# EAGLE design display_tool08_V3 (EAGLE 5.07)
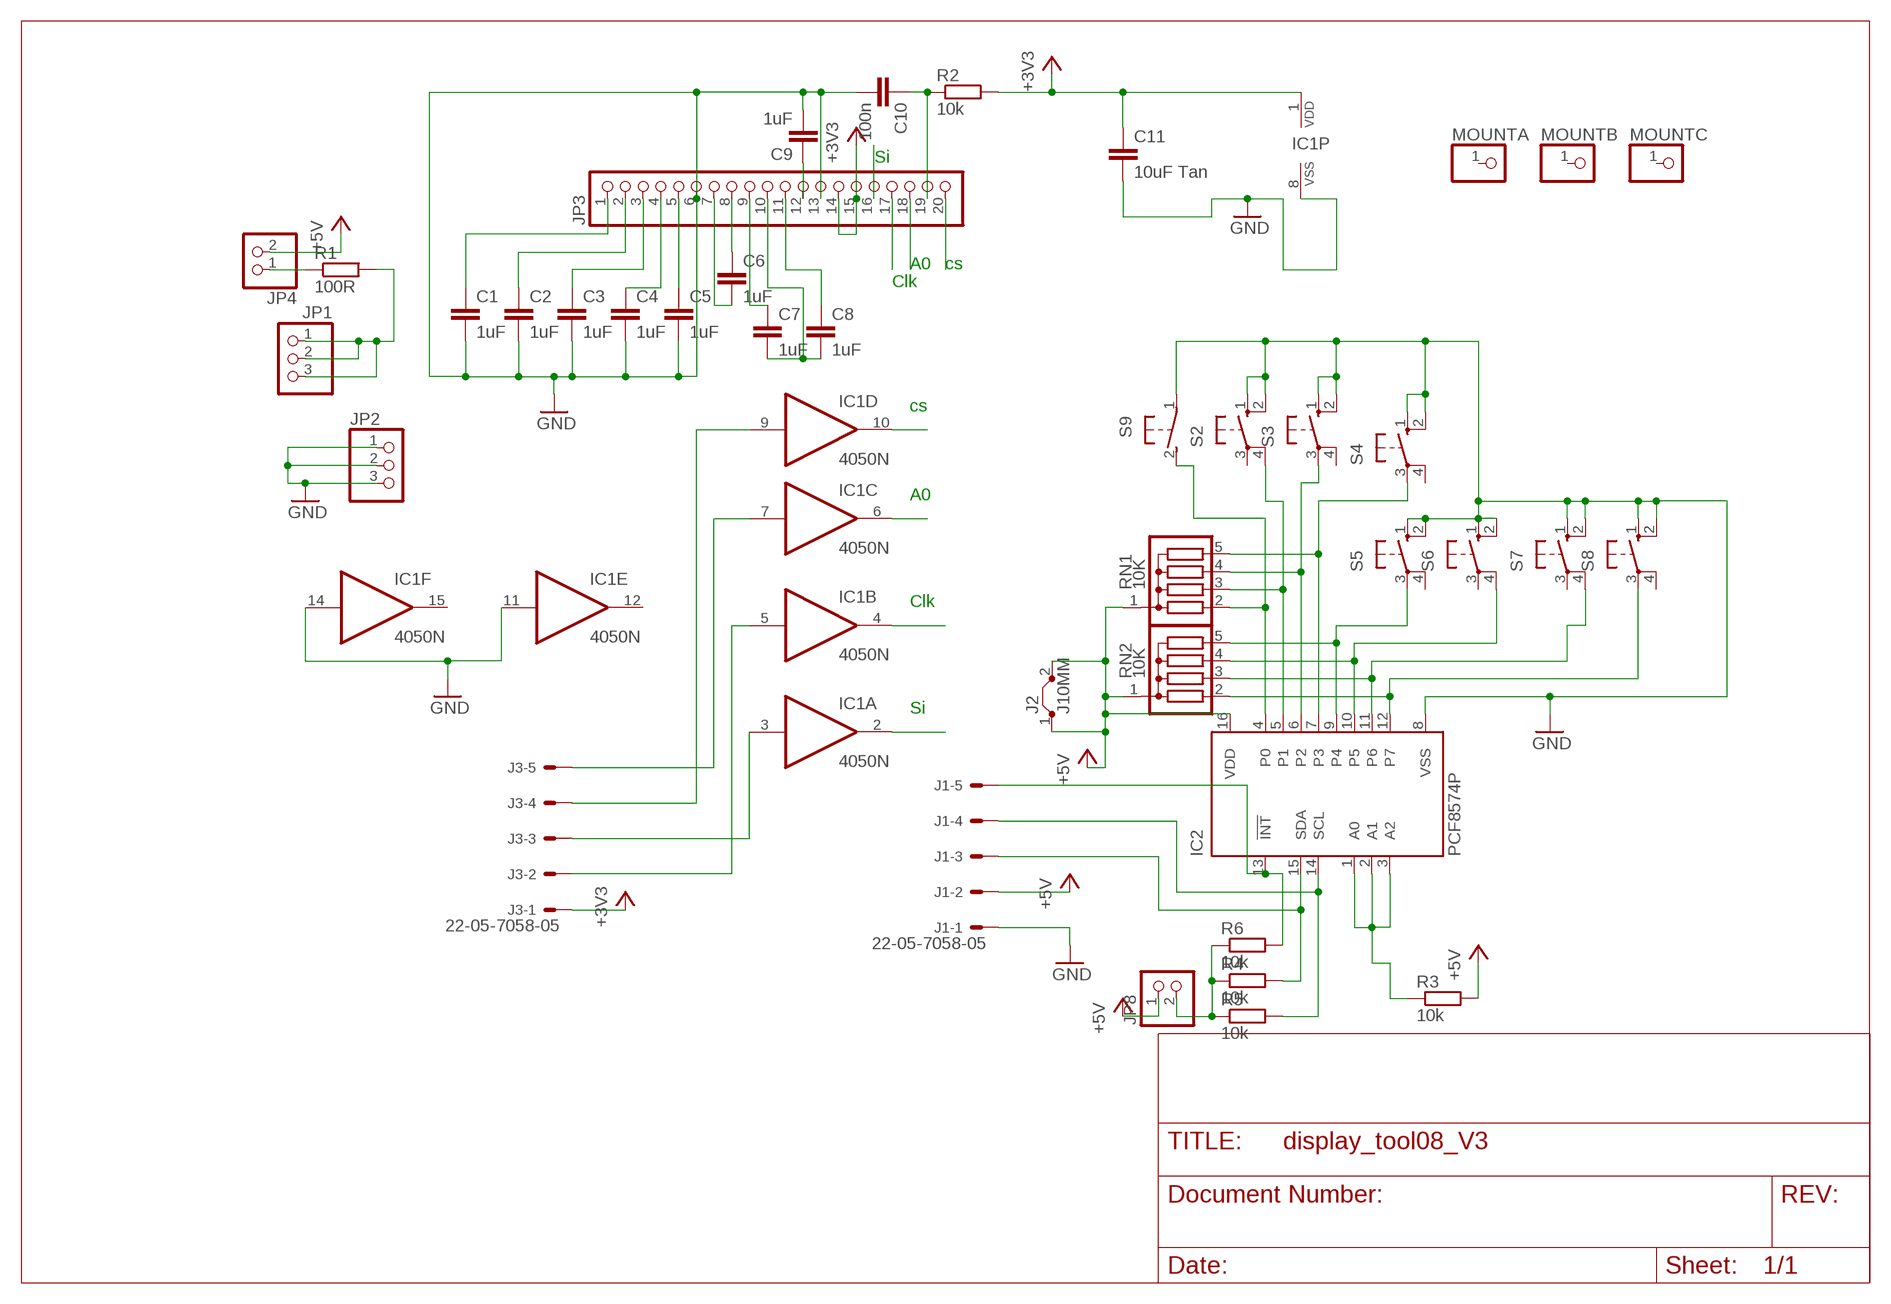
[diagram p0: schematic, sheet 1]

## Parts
C1  1uF  C-EU025-025X050  [C025-025X050]
C2  1uF  C-EU025-025X050  [C025-025X050]
C3  1uF  C-EU025-025X050  [C025-025X050]
C4  1uF  C-EU025-025X050  [C025-025X050]
C5  1uF  C-EU025-025X050  [C025-025X050]
C6  1uF  C-EU025-025X050  [C025-025X050]
C7  1uF  C-EU025-025X050  [C025-025X050]
C8  1uF  C-EU025-025X050  [C025-025X050]
C9  1uF  C-EU025-025X050  [C025-025X050]
C10  100n  C-EU025-025X050  [C025-025X050]
C11  10uF Tan  C-EU025-025X050  [C025-025X050]
IC1  4050N  [DIL16]
IC2  PCF8574P  [DIL16]
J1  22-05-7058-05  [7395-05]
J2  J10MM  [10]
J3  22-05-7058-05  [7395-05]
JP1  PINHD-1X3  [1X03]
JP2  PINHD-1X3  [1X03]
JP3  PINHD-1X20  [1X20]
JP4  PINHD-1X2  [1X02]
JP8  PINHD-1X2  [1X02]
MOUNTA  PINHD-1X1  [1X01]
MOUNTB  PINHD-1X1  [1X01]
MOUNTC  PINHD-1X1  [1X01]
R1  100R  R-EU_0309/12  [0309/12]
R2  10k  R-EU_0309/12  [0309/12]
R3  10k  R-EU_0207/7  [0207/7]
R4  10k  R-EU_0207/7  [0207/7]
R5  10k  R-EU_0207/7  [0207/7]
R6  10k  R-EU_0207/7  [0207/7]
RN1  10K  G04R  [SIL5]
RN2  10K  G04R  [SIL5]
S2  10-XX  [B3F-10XX]
S3  10-XX  [B3F-10XX]
S4  10-XX  [B3F-10XX]
S5  10-XX  [B3F-10XX]
S6  10-XX  [B3F-10XX]
S7  10-XX  [B3F-10XX]
S8  10-XX  [B3F-10XX]
S9  31-XX  [B3F-31XX]

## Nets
+3V3: C11.1 IC1.1(P:VDD) J3.1 JP3.14 JP3.15 R2.2
+5V: IC2.16(VDD) J1.2 J2.1 J2.2 JP4.2 JP8.1 R3.2 RN1.1 RN2.1
A0: IC1.6(C:O) JP3.18
CLK: IC1.4(B:O) JP3.17
CS [signal]: IC1.10(D:O) JP3.20
GND: C1.2 C2.2 C3.2 C4.2 C5.2 C9.2 C10.2 C11.2 IC1.8(P:VSS) IC1.11(E:I) IC1.14(F:I) IC2.8(VSS) J1.1 JP2.1 JP2.2 JP2.3 JP3.6 JP3.13 S2.1(S) S2.2(S1) S3.1(S) S3.2(S1) S4.1(S) S4.2(S1) S5.1(S) S5.2(S1) S6.1(S) S6.2(S1) S7.1(S) S7.2(S1) S8.1(S) S8.2(S1) S9.1(P)
N$1: JP4.1 R1.1
N$2: JP1.1 JP1.2 JP1.3 R1.2
N$3: IC2.7(P3) RN1.5 S4.3(P)
N$4: IC2.12(P7) RN2.2 S8.3(P)
N$5: C1.1 JP3.1
N$6: C2.1 JP3.2
N$7: C3.1 JP3.3
N$8: C4.1 JP3.4
N$9: C5.1 JP3.5
N$10: IC2.6(P2) RN1.4 S3.3(P)
N$11: IC2.11(P6) RN2.3 S7.4(P1)
N$12: C6.2 JP3.7
N$13: C6.1 JP3.8
N$14: C7.2 C8.2 JP3.10
N$15: IC2.5(P1) RN1.3 S2.4(P1)
N$16: C7.1 JP3.9
N$17: C8.1 JP3.11
N$18: C9.1 JP3.12
N$19: C10.1 JP3.19 R2.1
N$20: IC2.10(P5) RN2.4 S6.4(P1)
N$21: IC2.4(P0) RN1.2 S9.2(S)
N$22: IC2.9(P4) RN2.5 S5.3(P)
N$25 [signal]: IC1.3(A:I) J3.3
N$26 [signal]: IC1.5(B:I) J3.2
N$27 [signal]: IC1.7(C:I) J3.5
N$28 [signal]: IC1.9(D:I) J3.4
N$30: IC2.13(!INT) J1.5 R6.2
N$31: IC2.1(A0) IC2.2(A1) IC2.3(A2) R3.1
N$35: JP8.2 R4.1 R5.1 R6.1
SCL: IC2.14(SCL) J1.4 R5.2
SDA: IC2.15(SDA) J1.3 R4.2
SI: IC1.2(A:O) JP3.16
Unconnected: IC1.12(E:O) IC1.15(F:O) MOUNTA.1 MOUNTB.1 MOUNTC.1 S2.3(P) S3.4(P1) S4.4(P1) S5.4(P1) S6.3(P) S7.3(P) S8.4(P1)

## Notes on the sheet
- Si
- A0 | cs
- Clk
- cs
- A0
- Clk
- Si

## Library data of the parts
C1-C11 = rcl:C-EU: CAPACITOR, European symbol
IC1 = 40xx:4050: Hex non-inverting BUFFER
IC2 = micro-philips:PCF8574: I2C-Bus Remote 8-bit I/O expander http://www.semiconductors.philips.com/acrobat_download/datasheets/PCF8574_4.pdf
J1 J3 = con-molex:22-?-05: CONNECTOR wire to board 2.54 mm (.1 inch) pitch header
J2 = jumper:J: Bridge
JP1 JP2 = pinhead:PINHD-1X3: PIN HEADER
JP3 = pinhead:PINHD-1X20: PIN HEADER
JP4 JP8 = pinhead:PINHD-1X2: PIN HEADER
MOUNTA MOUNTB MOUNTC = pinhead:PINHD-1X1: PIN HEADER
R1-R6 = rcl:R-EU_: RESISTOR, European symbol
RN1 RN2 = resistor-sil:G04R: SIL RESISTOR
S2-S8 = switch-omron:10-XX: OMRON SWITCH
S9 = switch-omron:31-XX: OMRON SWITCH

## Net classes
0 default: width 1.016 mm, drill 1.016 mm, clearance 0.635 mm
1 signal: width 0.889 mm, drill 1.016 mm, clearance 0.635 mm to class 0, clearance 0.635 mm

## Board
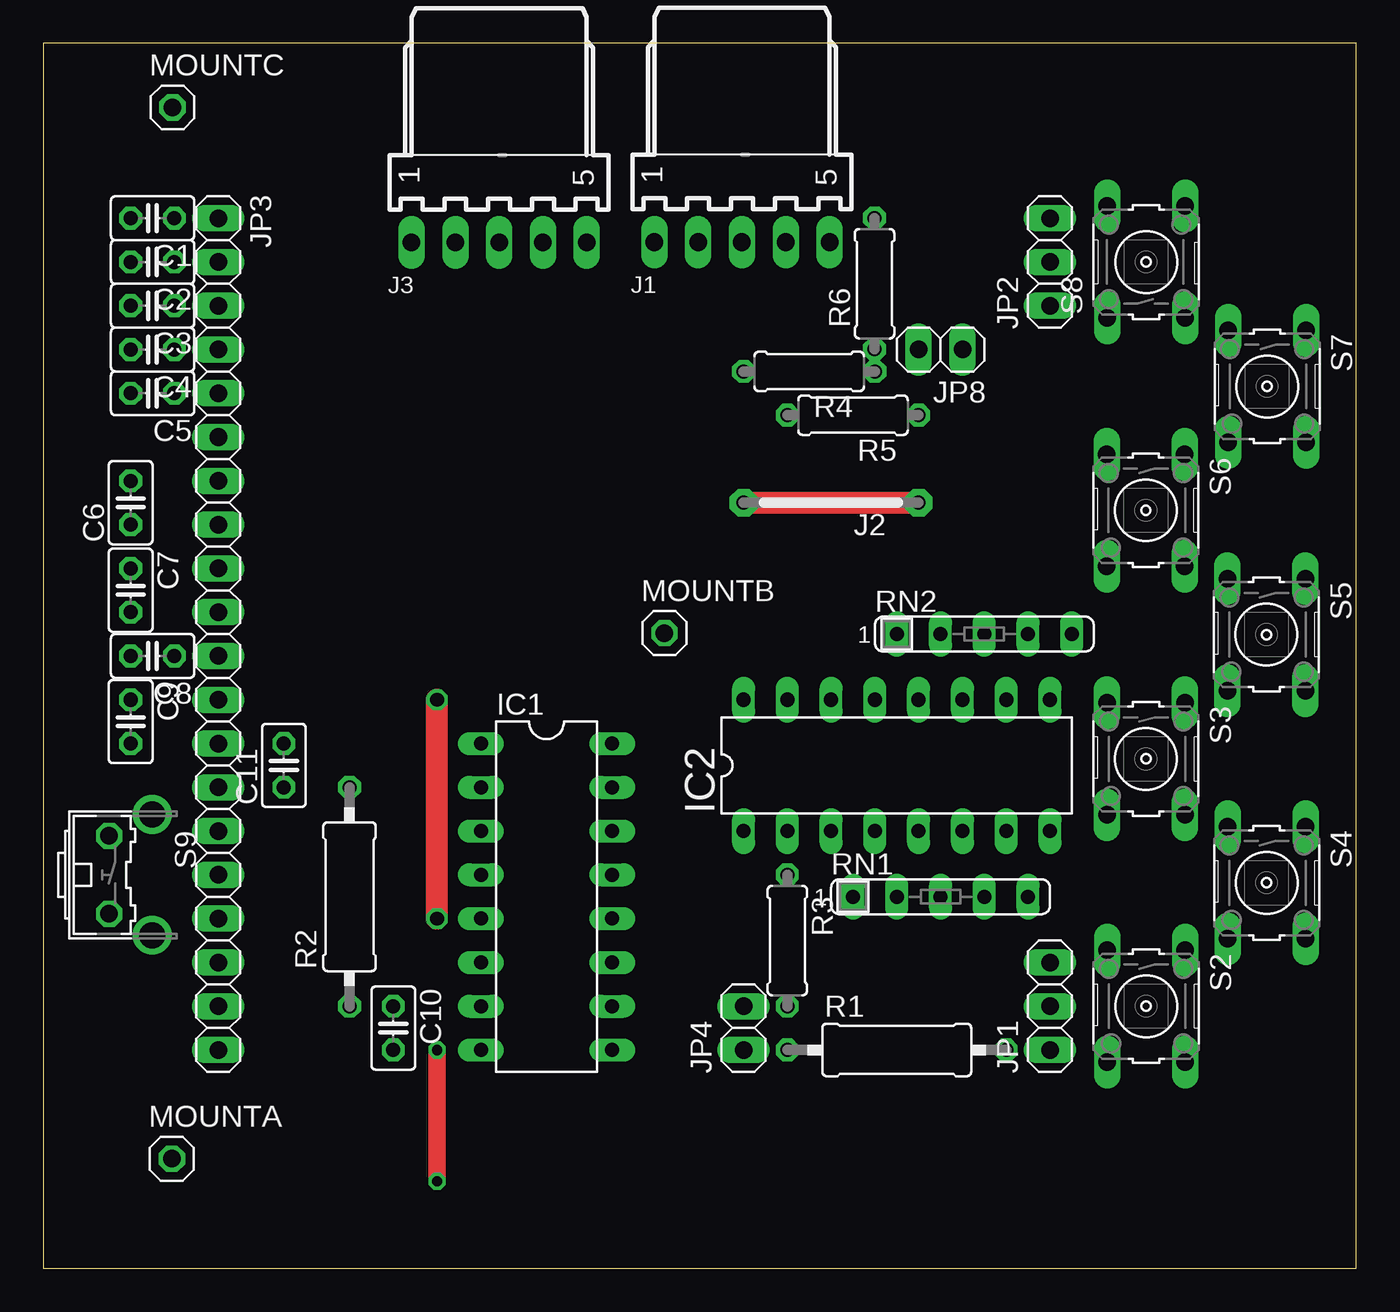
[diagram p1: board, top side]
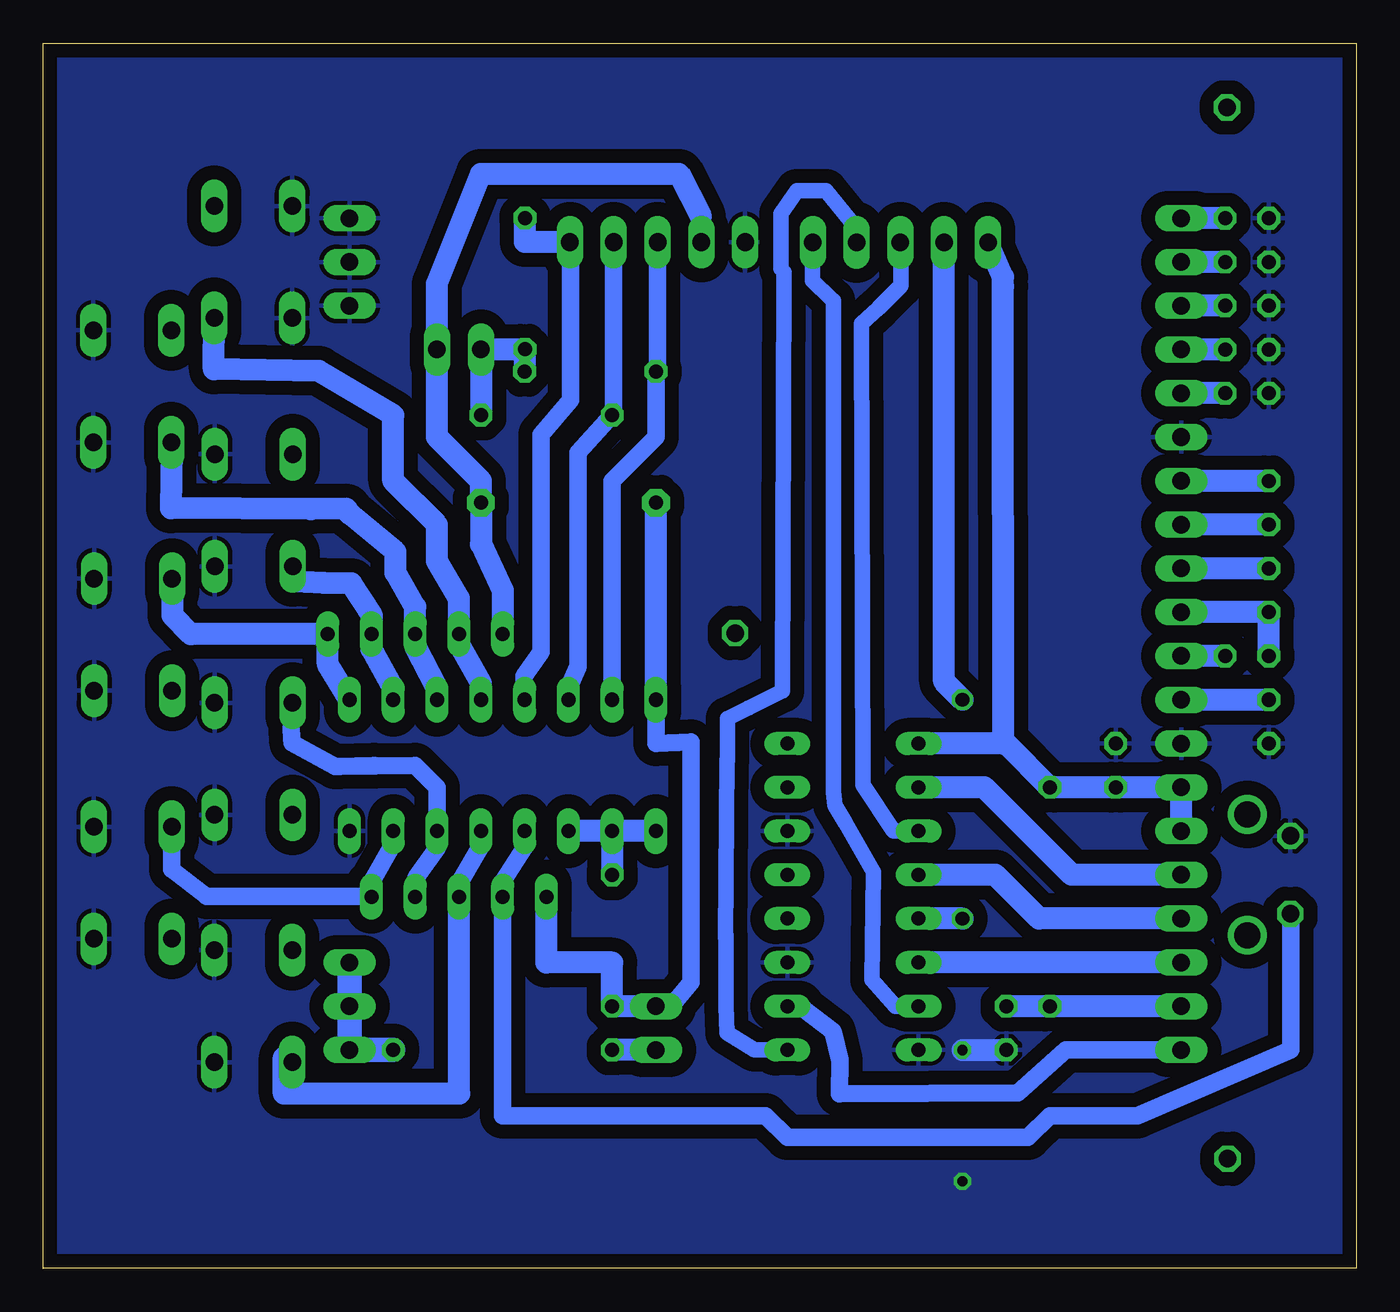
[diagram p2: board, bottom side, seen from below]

Size 76.2 x 71.12 mm. Coordinates in mm from the lower left corner, seen from the top.
Outline: 76.19,0.03 0,0.03 0,71.12 76.2,71.12 76.2,0
Copper layers (1*16): Top 0.035mm / dielectric 1.5mm / Bottom 0.035mm
Design rules "default *": minimum track width 10mil, minimum drill 24mil, track to track 8mil, track to pad 8mil, pad to pad 8mil, via to via 8mil, smd to smd 8mil, copper to edge 25mil, drill to drill 8mil, minimum pad ring 10mil, minimum via ring 8mil, stop-mask expansion 4mil, vias tented up to drill 0mil, thermal gap 10mil

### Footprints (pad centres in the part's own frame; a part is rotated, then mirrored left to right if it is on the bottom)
C025-025X050 = drill 0.813 octagon: 1 -1.27,0; 2 1.27,0
DIL16 = drill 0.813 long: 1 -8.89,-3.81; 2 -6.35,-3.81; 3 -3.81,-3.81; 4 -1.27,-3.81; 5 1.27,-3.81; 6 3.81,-3.81; 7 6.35,-3.81; 8 8.89,-3.81; 9 8.89,3.81; 10 6.35,3.81; 11 3.81,3.81; 12 1.27,3.81; 13 -1.27,3.81; 14 -3.81,3.81; 15 -6.35,3.81; 16 -8.89,3.81
7395-05 = drill 1.016 long: 1 5.08,0; 2 2.54,0; 3 0,0; 4 -2.54,0; 5 -5.08,0
10 = drill 0.813 pad 1.6 octagon: 1 -5.08,0; 2 5.08,0
1X03 = drill 1.016 long: 1 -2.54,0; 2 0,0; 3 2.54,0
1X20 = drill 1.016 long: 1 -24.13,0; 2 -21.59,0; 3 -19.05,0; 4 -16.51,0; 5 -13.97,0; 6 -11.43,0; 7 -8.89,0; 8 -6.35,0; 9 -3.81,0; 10 -1.27,0; 11 1.27,0; 12 3.81,0; 13 6.35,0; 14 8.89,0; 15 11.43,0; 16 13.97,0; 17 16.51,0; 18 19.05,0; 19 21.59,0; 20 24.13,0
1X02 = drill 1.016 long: 1 -1.27,0; 2 1.27,0
1X01 = drill 1.016 octagon: 1 0,0
0309/12 = drill 0.813 octagon: 1 -6.35,0; 2 6.35,0
0207/7 = drill 0.813 octagon: 1 -3.81,0; 2 3.81,0
SIL5 = drill 0.813 long: 1 -5.08,0; 2 -2.54,0; 3 0,0; 4 2.54,0; 5 5.08,0
B3F-10XX = drill 1.016 long: 1 -3.251,2.261; 2 3.251,2.261; 3 -3.251,-2.261; 4 3.251,-2.261
B3F-31XX = drill 1.016 octagon: 1 -2.261,-1.245; 2 2.261,-1.245 | drill 1.499 pad 2.159 round: 3 -3.505,1.245; 4 3.505,1.245

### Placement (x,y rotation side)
C1  6.35,60.96 180 top
C2  6.35,58.42 180 top
C3  6.35,55.88 180 top
C4  6.35,53.34 180 top
C5  6.35,50.8 180 top
C6  5.08,44.45 90 top
C7  5.08,39.37 270 top
C8  6.35,35.56 180 top
C9  5.08,31.75 270 top
C10  20.32,13.97 270 top
C11  13.97,29.21 90 top
IC1  29.21,21.59 270 top
IC2  49.53,29.21 0 top
J1  40.55,59.57 180 top
J2  45.72,44.45 180 top
J3  26.46,59.55 180 top
JP1  58.42,15.24 90 top
JP2  58.42,58.42 90 top
JP3  10.16,36.83 270 top
JP4  40.64,13.97 90 top
JP8  52.07,53.34 180 top
MOUNTA  7.47,6.39 0 top
MOUNTB  36.05,36.89 0 top
MOUNTC  7.51,67.39 0 top
R1  49.53,12.7 0 top
R2  17.78,21.59 90 top
R3  43.18,19.05 270 top
R4  44.45,52.07 180 top
R5  46.99,49.53 180 top
R6  48.24,57.16 90 top
RN1  52.07,21.59 0 top
RN2  54.61,36.83 0 top
S2  64,15.24 270 top
S3  63.99,29.59 270 top
S4  70.99,22.4 270 top
S5  70.98,36.8 270 top
S6  63.98,44.01 270 top
S7  71.02,51.2 270 top
S8  64,58.42 90 top
S9  5.08,22.86 270 top

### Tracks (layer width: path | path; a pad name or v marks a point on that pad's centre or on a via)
+3V3
  Bottom 1.016: J3.1
  Bottom 1.27: JP3.15 JP3.14 C11.1 R2.2 20.32,30.48 20.49,30.48 | 20.49,30.48 IC1.1 | 20.49,30.48 20.5,57 20.5,57.54 J3.1
+5V
  Top 1.27: J2.2 J2.1
  Bottom 1.016: IC2.16 40.64,30.48 38.6,30.58 38.6,16.61 39.77,15.24 | J1.2 38,59.6 38,60.45 38.04,61.06
  Bottom 1.27: RN1.1 46.99,17.78 43.18,17.78 R3.2 JP4.2 39.77,15.24 | 38.04,61.06 39.31,63.53 50.8,63.53 53.34,57.15 JP8.1 53.34,48.26 50.8,45.72 J2.1 50.8,42.04 49.53,39.37 RN2.1 | IC2.16 J2.2
A0
  Bottom 1.27: JP3.18 IC1.6
CLK
  Bottom 1.27: JP3.17 18.41,20.32 20.95,22.86 IC1.4
CS
  Bottom 1.016: IC1.10 32.08,15.07 30.36,13.77 29.96,12.1 29.98,10.16 19.65,10.2 16.87,12.7 JP3.20
GND  (via drill 0.6)
  Top 1.016: v22.86,5.08 v22.86,12.7
  Bottom 1.27: v22.86,12.7 C10.2
  pour Bottom (isolate 0.813): 0,71.12 76.2,71.12 76.2,0 0,0
N$1
  Bottom 1.27: JP4.1 R1.1
N$2
  Bottom 0.762: JP1.2
  Bottom 1.27: JP1.2
  Bottom 1.422: JP1.2 JP1.1 R1.2 | JP1.2 JP1.3
N$3
  Bottom 0.762: 55.91,24.6 55.91,25.4 IC2.7 | 57.11,21.6 RN1.5 57.51,21.6
  Bottom 1.016: 57.11,21.6 57.11,22.5 55.91,24.6 | 57.51,21.6 66.71,21.6 68.73,23.17 68.75,23.75 S4.3
N$4
  Bottom 1.27: IC2.12 50.8,33.99 52.07,36.26 RN2.2 52.07,38.9 53.34,41.07 53.34,43.18 55.88,45.72 55.88,49.53 60.2,52.1 66.3,52.2 S8.3
N$5
  Bottom 1.27: C1.1 JP3.1
N$6
  Bottom 1.27: C2.1 JP3.2
N$7
  Bottom 1.27: C3.1 JP3.3
N$8
  Bottom 1.27: C4.1 JP3.4
N$9
  Bottom 1.27: C5.1 JP3.5
N$10
  Bottom 0.762: 54.56,22.7 54.61,22.5 RN1.4 | 53.31,24.45 53.31,25.4 IC2.6
  Bottom 1.016: 54.56,22.7 53.31,24.45 | IC2.6 53.34,27.94 54.61,29.21 59,29.15 57,29.2 59.25,29.15 61.75,30.5 | 61.75,30.5 61.76,30.59 | S3.3 61.8,31.2 arc-4 61.75,30.5
N$11
  Bottom 1.016: 68.72,47.55 S7.4
  Bottom 1.27: IC2.11 53.34,33.69 54.61,36.16 RN2.3 54.61,38.4 55.76,40.4 55.76,41.61 58.42,43.81 58.6,44.1 60.66,44.08 68.77,44.13 68.72,47.55
N$12
  Bottom 1.27: C6.2 JP3.7
N$13
  Bottom 1.27: C6.1 JP3.8
N$14
  Bottom 1.27: JP3.10 C7.2 C8.2
N$15
  Bottom 0.762: 52.06,22.35 RN1.3 | 50.81,24.5 IC2.5
  Bottom 1.016: 52.06,22.35 50.81,24.5
  Bottom 1.27: RN1.3 52.06,10.17 52.07,10.16 62.23,10.16 62.23,12.27 S2.4
N$16
  Bottom 1.27: C7.1 JP3.9
N$17
  Bottom 1.27: C8.1 JP3.11
N$18
  Bottom 1.27: C9.1 JP3.12
N$19
  Bottom 1.016: R2.1 20.35,15.25 20.35,15.24
  Bottom 1.27: JP3.19 R2.1 C10.1 20.35,15.24
N$20
  Bottom 1.016: S6.4 61.75,39.9 61.64,39.88
  Bottom 1.27: IC2.10 55.88,33.69 57.15,35.96 RN2.4 57.12,37.9 58.32,39.77 59.95,39.8 61.64,39.88
N$21
  Bottom 0.762: 48.26,24.45 IC2.4 | 49.51,22.5 49.51,21.6 RN1.2
  Bottom 1.016: 49.51,22.5 48.26,24.45 | RN1.2 49.53,8.89 34.29,8.89 33.02,7.62 19.05,7.62 17.78,8.89 12.7,8.89 3.81,12.7 3.8,13.1 3.8,20.6 S9.2
N$22
  Bottom 1.27: IC2.9 59.69,35.09 RN2.5 67.63,36.83 68.69,37.92 S5.3
N$25
  Bottom 0.889: IC1.3 25.42,25.42 26.86,25.42 28.62,28.08 28.72,54.84 27.74,55.74 26.44,57.04 26.44,59.64 J3.3
N$26  (via drill 0.8 pad 1.02)
  Top 1.27: v22.86,20.32 v22.86,33.02
  Bottom 1.27: J3.2 23.92,34.08 v22.86,33.02 | v22.86,20.32 IC1.5
N$27
  Bottom 0.889: IC1.7 25.42,15.22 26.76,15.22 28.12,16.78 28.02,23.02 29.66,25.86 30.26,26.9 30.34,27.68 30.34,56.18 30.5,56.28 31.56,57.34 31.56,59.54 J3.5
N$28
  Bottom 0.889: IC1.9 34.92,12.7 36.52,13.7 36.58,15.26 36.58,18.98 36.6,19.98 36.62,19.2 36.52,29.56 36.5,29.46 36.5,31.94 35.28,32.54 33.3,33.52 33.2,57.84 33.4,58.04 33.4,61.22 32.46,62.56 30.78,62.56 29,60.38 J3.4
N$30
  Bottom 1.016: J1.5 45.6,59.57 45.6,50.4 47.3,48.4 47.3,35.8 48.3,34.4 48.3,33.18 IC2.13
  Bottom 1.27: J1.5 48.24,59.57 R6.2
N$31
  Bottom 1.27: IC2.1 IC2.2 | IC2.2 IC2.3 | IC2.2 R3.1
N$35
  Bottom 1.27: R5.1 JP8.2 R6.1 48.26,53.35 R4.1
SCL
  Bottom 1.016: IC2.14 45.72,33.69 45.15,34.96 45.15,47.36 R5.2 43.09,49.53 J1.4
SDA
  Bottom 1.016: IC2.15 43.18,45.72 40.64,48.26 R4.2 40.55,52.07 J1.3
SI
  Bottom 1.27: JP3.16 16.51,22.86 19.05,25.4 19.09,25.45 21.59,27.94 IC1.2

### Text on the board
bText: WWW.SAMMELLOTHAR.DE | EMC2 PENDANT GLCD | WWW.LINUXCNC.ORG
